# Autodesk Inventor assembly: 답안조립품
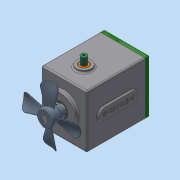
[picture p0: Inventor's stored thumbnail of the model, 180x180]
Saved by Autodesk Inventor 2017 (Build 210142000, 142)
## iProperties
Part Number: 답안조립품
Material: 일반
Document SubType Name: Assembly
Designer: MRC
Mass: 2663.34 g
Surface Area: 1952.92 cm^2
Volume: 798.897 cm^3
Density: 3.33377 g/cm^3
Author: MRC
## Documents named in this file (17)
- C:\Users\MRC\Desktop\610205V1006\답안조립품.iam
- C:\Users\MRC\Desktop\610205V1006\본체.ipt
- C:\Users\MRC\Desktop\610205V1006\가변스프링.ipt
- C:\Users\MRC\Desktop\610205V1006\멈춤나사 M3x8.ipt
- C:\Users\MRC\Desktop\610205V1006\메인 기어 축.ipt
- C:\Users\MRC\Desktop\610205V1006\베어링 608.ipt
- C:\Users\MRC\Desktop\610205V1006\베어링 6903.ipt
- C:\Users\MRC\Desktop\610205V1006\볼트 M4 x 10.ipt
- C:\Users\MRC\Desktop\610205V1006\부시.ipt
- C:\Users\MRC\Desktop\610205V1006\서브 기어 축.ipt
- C:\Users\MRC\Desktop\610205V1006\슬라이더.ipt
- C:\Users\MRC\Desktop\610205V1006\오일 실 8 22 7.ipt
- C:\Users\MRC\Desktop\610205V1006\오일 실 17 30 8.ipt
- C:\Users\MRC\Desktop\610205V1006\커버.ipt
- C:\Users\MRC\Desktop\610205V1006\키 5 x 5 x 24.ipt
- C:\Users\MRC\Desktop\610205V1006\팬날개.ipt
- 팬날개.ipt
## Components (1 placed, 1 different names)
1. 가변스프링:1
